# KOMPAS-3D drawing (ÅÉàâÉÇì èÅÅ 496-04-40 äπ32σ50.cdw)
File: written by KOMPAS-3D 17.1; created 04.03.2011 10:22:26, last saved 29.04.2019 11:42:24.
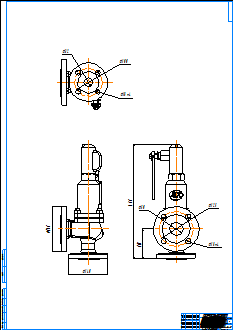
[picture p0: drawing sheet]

Sheet 1: A0, portrait

Title block, sheet 1: name: Прегран Ду 32х50; material: Внимание! Данный продукт является объектом авторского права ООО «Торговый Дом АДЛ». / Запрещается изменение, копирование, распространение / (в том числе путем копирования на другие сайты и ресурсы в Интернете) / или любое иное использование информации и объектов без предварительного / согласия правообладателя (ООО «Торговый Дом АДЛ»).; scale: 1:1; sheets: 1; organisation: ООО "Торговый дом АДЛ"; sheet format: A0; stored path: C:\Users\tra\Desktop\2д чертежи\Предохранительные клапаны ПРЕГРАН\ПРЕГРАН 496\ПРЕГРАН КПП 496-04-40\KOMPAS 2D\Прегран Ду 32х50.cdw

Views: Спереди 1, Проекционный вид 2, Проекционный вид 3
Dimensions and other numbers on the sheet: 110; 125; 18; 50; 140; 165; 420; 100; 32; 1:1; 1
